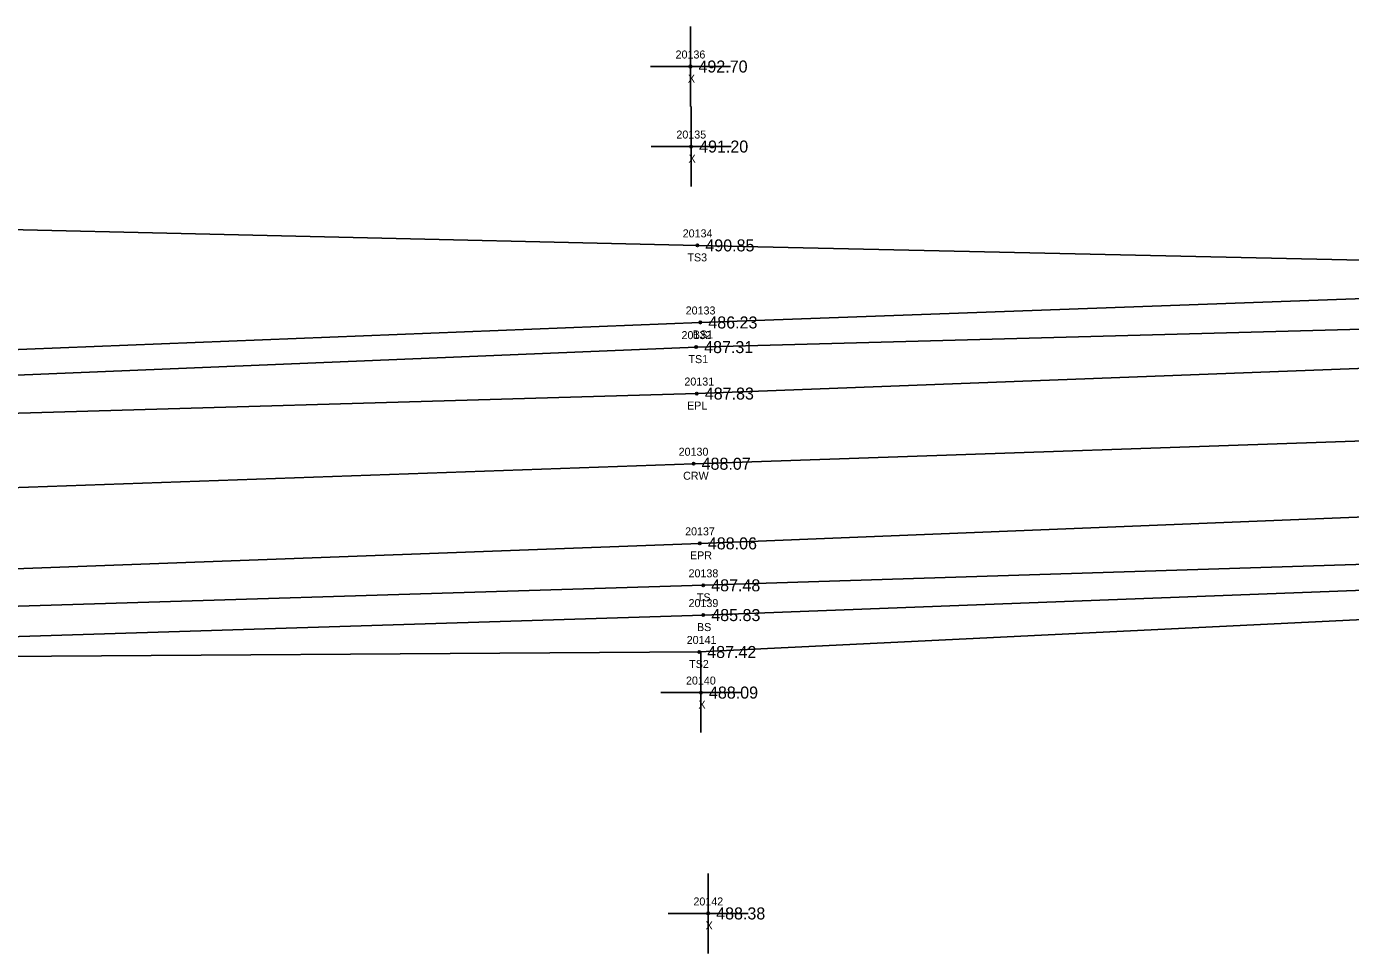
# Model space of a CAD drawing. Extents: x 1785066 to 1786589, y 770293 to 771312.
# Drawn here: x 1785397.2 to 1785562.6, y 770782.7 to 770898.6 of the extents above; entities that cross this region are included whole.
import ezdxf

# ---------------------------------------------------------------- set-up
doc = ezdxf.new("R2010")
doc.units = 0
for name, color, linetype in [('RD_DTM_BkLn1', 7, 'Continuous'), ('RD_DTM_BkLn2', 7, 'Continuous'), ('RD_DTM_BkLn_txCode', 7, 'Continuous'), ('RD_EX_Misc', 7, 'Continuous'), ('RD_EX_Misc_txCode', 7, 'Continuous'), ('RD_EX_Road', 7, 'Continuous'), ('RD_EX_Road_txCode', 7, 'Continuous'), ('RD_EX_TX_Misc_ELEV', 7, 'Continuous'), ('RD_EX_TX_Road_ELEV', 7, 'Continuous'), ('RD_HC_Survey_ELEV', 7, 'Continuous'), ('RD_HC_Survey_txCode', 7, 'Continuous'), ('RD_SMD_Locator', 7, 'Continuous')]:
    doc.layers.add(name, color=color, linetype=linetype)

msp = doc.modelspace()

# ---------------------------------------------------------------- linework, layer by layer
at = {"layer": 'RD_DTM_BkLn1'}
msp.add_lwpolyline([(1785082.06, 770851.29), (1785131.3, 770843.85), (1785181.17, 770839.05), (1785231.06, 770837.12), (1785280.99, 770837.06), (1785330.97, 770838.45), (1785380.81, 770840.43), (1785480.56, 770843.94), (1785580.22, 770847.33), (1785679.99, 770850.66), (1785779.91, 770853.54)], dxfattribs=at)
at = {"layer": 'RD_DTM_BkLn2'}
for points in [[(1785219, 770887.48), (1785221.61, 770869.17), (1785226.44, 770862.44), (1785230.83, 770863.64), (1785281.61, 770865.88), (1785330.18, 770866.95), (1785380.62, 770873.53), (1785481.03, 770871.22), (1785579.17, 770869.06), (1785678.49, 770873.66), (1785753.25, 770880.69), (1785777.57, 770887.66), (1785796.72, 770894.6)], [(1785221.18, 770856.06), (1785231.29, 770855.17), (1785280.9, 770855.5), (1785330.48, 770855.32), (1785380.39, 770857.59), (1785481.4, 770861.59), (1785579.34, 770865.13), (1785679.06, 770868.59), (1785753.94, 770876.35), (1785778.96, 770883.81)], [(1785221.33, 770857.68), (1785219.57, 770857.18), (1785219.95, 770853.94), (1785231.29, 770851.96), (1785280.92, 770852.98), (1785330.39, 770854.04), (1785380.75, 770854.37), (1785480.88, 770858.51), (1785579.51, 770861.16), (1785679.28, 770865.65), (1785754.2, 770872.9), (1785779.7, 770881.19), (1785786.95, 770881.8), (1785789.14, 770878.77), (1785786.05, 770869.32), (1785786.11, 770839.44)], [(1785205.07, 770819.03), (1785219.41, 770822.94), (1785230.95, 770822.33), (1785281.39, 770822.23), (1785331.37, 770822.34), (1785381.2, 770825.69), (1785481.76, 770828.75), (1785580.39, 770831.91), (1785680.81, 770834.37), (1785757.11, 770838.03), (1785775.28, 770836.8), (1785785.27, 770835.59), (1785786.11, 770839.44)], [(1785217.48, 770818.88), (1785230.53, 770818.92), (1785281.87, 770818.54), (1785331.33, 770820.31), (1785381.53, 770821.9), (1785481.77, 770825.03), (1785580.88, 770828.75), (1785679.45, 770830.28), (1785757.48, 770831.63), (1785774.02, 770829.34), (1785791.05, 770829.99), (1785795.95, 770830.77)], [(1785205.07, 770819.03), (1785218.74, 770813.87), (1785230.3, 770814.87), (1785282.58, 770814.55), (1785331.23, 770817.62), (1785381.61, 770819.76), (1785481.26, 770820.42), (1785579.63, 770825.21), (1785679.72, 770826.75), (1785756.33, 770825.6), (1785774.03, 770825.73), (1785791.3, 770827.72), (1785795.65, 770828.98)]]:
    msp.add_lwpolyline(points, dxfattribs=at)
at = {"layer": 'RD_EX_Misc'}
for p, q in [((1785480.17, 770888.57), (1785480.17, 770898.57)), ((1785475.17, 770893.57), (1785485.17, 770893.57)), ((1785480.25, 770878.57), (1785480.25, 770888.57)), ((1785475.25, 770883.57), (1785485.25, 770883.57)), ((1785481.48, 770810.35), (1785481.48, 770820.35)), ((1785476.48, 770815.35), (1785486.48, 770815.35)), ((1785482.38, 770782.75), (1785482.38, 770792.75)), ((1785477.38, 770787.75), (1785487.38, 770787.75))]:
    msp.add_line(p, q, dxfattribs=at)
at = {"layer": 'RD_EX_Road'}
for points in [[(1785083.87, 770860.72), (1785132.91, 770853.08), (1785181.89, 770848.53), (1785200.96, 770847.97), (1785215.21, 770848.13), (1785231.38, 770846.18), (1785281.19, 770846.16), (1785330.68, 770847.27), (1785380.41, 770849.82), (1785480.96, 770852.71), (1785580.09, 770856.45), (1785680.2, 770859.84), (1785779.71, 770863.4)], [(1785079.74, 770841.1), (1785077.36, 770829.81), (1785127.59, 770822.23), (1785177.27, 770813.99), (1785180.45, 770828), (1785230.74, 770826.87), (1785281.16, 770827.18), (1785331.14, 770828.42), (1785381.03, 770830.27), (1785481.34, 770833.99), (1785580.1, 770837.94), (1785680.6, 770840.57), (1785780.28, 770843.87)]]:
    msp.add_lwpolyline(points, dxfattribs=at)
at = {"layer": 'RD_SMD_Locator'}
for centre in [(1785480.17, 770893.57), (1785480.25, 770883.57), (1785481.03, 770871.22), (1785481.4, 770861.59), (1785480.88, 770858.51), (1785480.96, 770852.71), (1785480.56, 770843.94), (1785481.34, 770833.99), (1785481.76, 770828.75), (1785481.77, 770825.03), (1785481.26, 770820.42), (1785481.48, 770815.35), (1785482.38, 770787.75)]:
    msp.add_circle(centre, 0.15, dxfattribs=at)

# ---------------------------------------------------------------- texts
at = {"layer": 'RD_DTM_BkLn_txCode'}
for s, p in [('20134', (1785479.2, 770872.22)), ('TS3', (1785479.79, 770869.22)), ('20133', (1785479.57, 770862.59)), ('20132', (1785479.05, 770859.51)), ('BS1', (1785480.46, 770859.59)), ('TS1', (1785479.92, 770856.51)), ('20138', (1785479.93, 770829.75)), ('TS', (1785480.97, 770826.75)), ('20139', (1785479.93, 770826.03)), ('BS', (1785480.99, 770823.03)), ('20141', (1785479.7, 770821.42)), ('TS2', (1785480.01, 770818.42))]:
    msp.add_text(s, height=1, dxfattribs=at).set_placement(p)
at = {"layer": 'RD_EX_Misc_txCode'}
for s, p in [('20136', (1785478.31, 770894.57)), ('X', (1785479.85, 770891.57)), ('20135', (1785478.41, 770884.57)), ('X', (1785479.93, 770881.57)), ('20140', (1785479.61, 770816.35)), ('X', (1785481.17, 770813.35)), ('20142', (1785480.54, 770788.75)), ('X', (1785482.06, 770785.75))]:
    msp.add_text(s, height=1, dxfattribs=at).set_placement(p)
at = {"layer": 'RD_EX_Road_txCode'}
for s, p in [('20131', (1785479.41, 770853.71)), ('EPL', (1785479.75, 770850.71)), ('20137', (1785479.5, 770834.99)), ('EPR', (1785480.11, 770831.99))]:
    msp.add_text(s, height=1, dxfattribs=at).set_placement(p)
at = {"layer": 'RD_EX_TX_Misc_ELEV'}
for s, p in [('492.70', (1785481.17, 770892.82)), ('491.20', (1785481.25, 770882.82)), ('490.85', (1785482.03, 770870.47)), ('486.23', (1785482.4, 770860.84)), ('487.31', (1785481.88, 770857.76)), ('487.48', (1785482.76, 770828)), ('485.83', (1785482.77, 770824.28)), ('487.42', (1785482.26, 770819.67)), ('488.09', (1785482.48, 770814.6)), ('488.38', (1785483.38, 770787))]:
    msp.add_text(s, height=1.5, dxfattribs=at).set_placement(p)
at = {"layer": 'RD_EX_TX_Road_ELEV'}
for s, p in [('487.83', (1785481.96, 770851.96)), ('488.06', (1785482.34, 770833.24))]:
    msp.add_text(s, height=1.5, dxfattribs=at).set_placement(p)
at = {"layer": 'RD_HC_Survey_ELEV'}
msp.add_text('488.07', height=1.5, dxfattribs=at).set_placement((1785481.56, 770843.19))
at = {"layer": 'RD_HC_Survey_txCode'}
for s, p in [('20130', (1785478.69, 770844.94)), ('CRW', (1785479.25, 770841.94))]:
    msp.add_text(s, height=1, dxfattribs=at).set_placement(p)

doc.saveas('drawing.dxf')
